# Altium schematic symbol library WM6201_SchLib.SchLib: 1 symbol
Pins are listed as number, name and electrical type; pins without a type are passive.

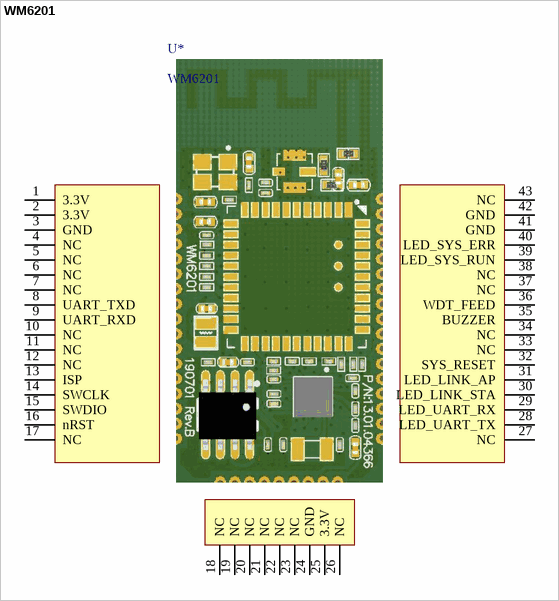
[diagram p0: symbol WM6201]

## WM6201
designator U*
pins: 1 3.3V, 2 3.3V, 3 GND, 4 NC, 5 NC, 6 NC, 7 NC, 8 UART_TXD, 9 UART_RXD, 10 NC, 11 NC, 12 NC, 13 ISP, 14 SWCLK, 15 SWDIO, 16 nRST, 17 NC, 18 NC, 19 NC, 20 NC, 21 NC, 22 NC, 23 NC, 24 GND, 25 3.3V, 26 NC, 27 NC, 28 LED_UART_TX, 29 LED_UART_RX, 30 LED_LINK_STA, 31 LED_LINK_AP, 32 SYS_RESET, 33 NC, 34 NC, 35 BUZZER, 36 WDT_FEED, 37 NC, 38 NC, 39 LED_SYS_RUN, 40 LED_SYS_ERR, 41 GND, 42 GND, 43 NC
